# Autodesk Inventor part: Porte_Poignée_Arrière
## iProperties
Created: 2009-01
Part Number: Porte_Poignée_Arrière
Document SubType Name: Modeling
Designer: claivier
Norme de conversion: STEP AP214IS
Nom du fichier: SW3dPS-P1-30-101-11_P1_CUP.STEP
Préprocesseur: SolidWorks 2008
Postprocesseur: Build: 344a, Release: 11 SP2 - Date: Fri 08/18/2006
Unités envoyées: MILLIMETERS
Incertitude: 1e-05
Author: claivier
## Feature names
1. Base1
